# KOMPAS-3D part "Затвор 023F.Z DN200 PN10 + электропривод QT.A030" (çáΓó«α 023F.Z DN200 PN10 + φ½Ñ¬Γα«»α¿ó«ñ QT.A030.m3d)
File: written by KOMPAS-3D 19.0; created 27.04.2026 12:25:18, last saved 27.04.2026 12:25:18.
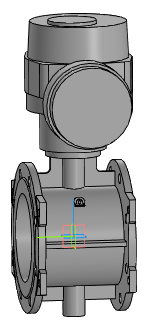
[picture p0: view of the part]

Document properties: Полное имя файла: Затвор 023F.Z DN200 PN10 + электропривод QT.A030.a3d

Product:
- Part/product: Затвор 023F.Z DN200 PN10 + электропривод QT.A030
    Масса: 155.518

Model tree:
1. Операция без истории:1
